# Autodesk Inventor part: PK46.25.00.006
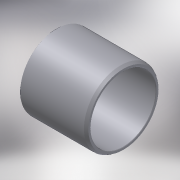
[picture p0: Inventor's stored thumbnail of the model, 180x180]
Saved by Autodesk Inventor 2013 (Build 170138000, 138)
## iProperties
Created: 2005-05
Part Number: PK46.25.00.006
Material: Steel, Mild
Document SubType Name: Modeling
Designer: PVitaliy
Manufacturer: Standard
Standards Organization: Custom
Density: 7.86 g/cm^3
Author: PVitaliy
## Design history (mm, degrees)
sketch "Эскиз2"
  geometry: L1 (0, 0)-(45.09, 0); L2 (0, 45)-(78.536, 45); L3 (0, 45)-(0, 40); L4 (0, 40)-(82, 40); L5 (82, 40)-(82, 43); L6 (78.536, 45)-(82, 43)
  constraints: 12 end point, 3 horizontal, 2 vertical, 1 point on line, 1 other
  dimensions: "d0" = 90 diameter of L2 L1; "d1" = 80 diameter of L4 L1; "d3" = 82 distance of L3.end L4.end; "d4" = 30 deg angle of L6 L2; "d5" = 86 diameter of L5.end L1
revolve "Вращение1" sketch "Эскиз2" stored, may be unused: angle "d6" = 90 deg
chamfer "Фаска1" distance "d7" = 0.5; stored, may be unused: second distance "d8" = 2, angle "d9" = 45 deg
body "Solid1"
